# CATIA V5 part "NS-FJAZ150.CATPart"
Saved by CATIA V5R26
Part number: NS-FJAZ150
Bounding box of the stored display mesh (mm): x -60 to 120, y 0 to 198, z -60 to 60
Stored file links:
  R:\Document\坂尻\その他\ナベヤデータ変換\安全カバーキャスター\MCBJSAZ150\NS-FJAZ150.CATPart
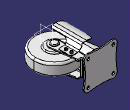
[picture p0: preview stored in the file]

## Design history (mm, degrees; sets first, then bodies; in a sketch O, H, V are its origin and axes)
Body1 (main body)
  Solid1: solid without history
  Body2
    Solid2: solid without history
  Assemble1: tool Body2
